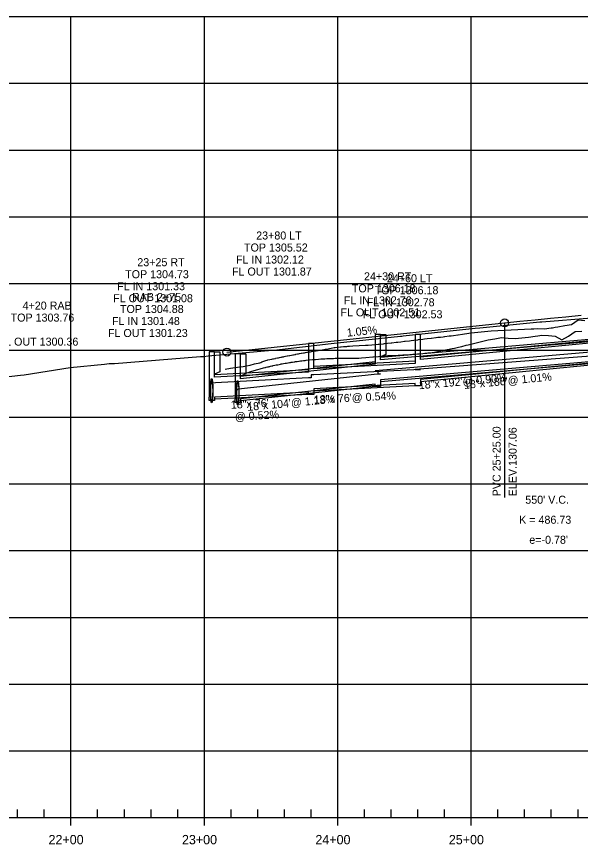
# Model space of a CAD drawing. Extents: x 670877 to 686811, y 705985 to 708501.
# Drawn here: x 685636 to 686059, y 707873 to 708493 of the extents above; entities that cross this region are included whole.
import ezdxf

# ---------------------------------------------------------------- set-up
doc = ezdxf.new("R2010")
doc.units = 0
for name, color, linetype in [('30', 7, 'Continuous'), ('37', 7, 'Continuous'), ('DRAINAGE_HGL LEFT', 7, 'Continuous'), ('DRAINAGE_HGL RIGHT', 7, 'Continuous'), ('Profile Drainage Annot Left', 7, 'Continuous'), ('Profile Drainage Annot Right', 7, 'Continuous'), ('R_Drainage Extensions_LEFT', 7, 'Continuous'), ('R_Drainage Extensions_RIGHT', 7, 'Continuous'), ('R_Drainage LEFT', 7, 'Continuous'), ('R_Drainage RIGHT', 7, 'Continuous'), ('R_Exist Surface', 7, 'Continuous'), ('R_Profile Work Left', 7, 'Continuous'), ('R_Proposed Const Limits', 7, 'Continuous'), ('R_Vert Alg', 7, 'Continuous'), ('R_Vert Alg Annot', 7, 'Continuous')]:
    doc.layers.add(name, color=color, linetype=linetype)

msp = doc.modelspace()

# ---------------------------------------------------------------- linework, layer by layer
at = {"layer": '37'}
for p, q in [((684477.28, 708492.85), (686777.28, 708492.85)), ((685677.28, 707892.85), (685677.28, 708492.85)), ((685777.28, 707892.85), (685777.28, 708492.85)), ((685877.28, 707892.85), (685877.28, 708492.85)), ((685977.28, 707892.85), (685977.28, 708492.85)), ((684477.28, 708442.85), (686777.28, 708442.85)), ((684477.28, 708392.85), (686777.28, 708392.85)), ((684477.28, 708342.85), (686777.28, 708342.85)), ((684477.28, 708292.85), (686777.28, 708292.85)), ((684477.28, 708242.85), (686777.28, 708242.85)), ((684477.28, 708192.85), (686777.28, 708192.85)), ((684477.28, 708142.85), (686777.28, 708142.85)), ((684477.28, 708092.85), (686777.28, 708092.85)), ((684477.28, 708042.85), (686777.28, 708042.85)), ((684477.28, 707992.85), (686777.28, 707992.85)), ((684477.28, 707942.85), (686777.28, 707942.85)), ((685637.28, 707892.85), (685637.28, 707898.85)), ((685657.28, 707892.85), (685657.28, 707898.85)), ((685697.28, 707892.85), (685697.28, 707898.85)), ((685717.28, 707892.85), (685717.28, 707898.85)), ((685737.28, 707892.85), (685737.28, 707898.85)), ((685757.28, 707892.85), (685757.28, 707898.85)), ((685797.28, 707892.85), (685797.28, 707898.85)), ((685817.28, 707892.85), (685817.28, 707898.85)), ((685837.28, 707892.85), (685837.28, 707898.85)), ((685857.28, 707892.85), (685857.28, 707898.85)), ((685897.28, 707892.85), (685897.28, 707898.85)), ((685917.28, 707892.85), (685917.28, 707898.85)), ((685937.28, 707892.85), (685937.28, 707898.85)), ((685957.28, 707892.85), (685957.28, 707898.85)), ((685997.28, 707892.85), (685997.28, 707898.85)), ((686017.28, 707892.85), (686017.28, 707898.85)), ((686037.28, 707892.85), (686037.28, 707898.85)), ((686057.28, 707892.85), (686057.28, 707898.85)), ((684477.28, 707892.85), (686777.28, 707892.85)), ((685677.28, 707886.85), (685677.28, 707892.85)), ((685777.28, 707886.85), (685777.28, 707892.85)), ((685877.28, 707886.85), (685877.28, 707892.85)), ((685977.28, 707886.85), (685977.28, 707892.85))]:
    msp.add_line(p, q, dxfattribs=at)
at = {"layer": 'DRAINAGE_HGL LEFT'}
msp.add_lwpolyline([(686452.28, 708277.68), (686454.28, 708277.68), (686454.28, 708277.68), (686454.28, 708277.68), (686340.29, 708272.6), (686342.29, 708272.6), (686342.29, 708264.29), (686344.29, 708264.29), (686125.29, 708244.79), (686127.29, 708244.79), (686127.29, 708243.32), (686129.3, 708243.32), (685935.28, 708228.55), (685937.28, 708228.55), (685937.28, 708228.55), (685939.3, 708228.55), (685859.24, 708224.45), (685857.24, 708224.45), (685857.24, 708222.25), (685855.24, 708222.25), (685780.74, 708218.25), (685782.77, 708218.25)], dxfattribs=at)
at = {"layer": 'DRAINAGE_HGL RIGHT'}
msp.add_lwpolyline([(686477.28, 708278.42), (686450.04, 708277.56), (686452.28, 708277.56), (686452.28, 708275.36), (686454.28, 708275.36), (686340.29, 708272.17), (686342.29, 708272.17), (686342.29, 708265.24), (686344.29, 708265.24), (686100.28, 708246.64), (686102.28, 708246.64), (686102.28, 708244.78), (686104.28, 708244.78), (685905.28, 708227.58), (685907.28, 708227.58), (685907.28, 708225.28), (685909.33, 708225.28), (685800.25, 708213.48), (685802.28, 708213.48)], dxfattribs=at)
at = {"layer": 'R_Drainage Extensions_LEFT'}
msp.add_lwpolyline([(685784.8, 708241.65), (685788.8, 708241.65), (685788.8, 708226.65), (685784.8, 708224.98), (685784.8, 708241.65)], dxfattribs=at)
at = {"layer": 'R_Drainage Extensions_RIGHT'}
for points in [[(685909.3, 708254.65), (685913.3, 708254.65), (685913.3, 708239.65), (685909.3, 708237.98), (685909.3, 708254.65)], [(685804.31, 708240.15), (685808.31, 708240.15), (685808.31, 708225.15), (685804.31, 708223.48), (685804.31, 708240.15)]]:
    msp.add_lwpolyline(points, dxfattribs=at)
at = {"layer": 'R_Drainage LEFT'}
for points in [[(685939.29, 708254.65), (685935.28, 708254.65)], [(685935.28, 708254.65), (685935.28, 708232.94)], [(686125.28, 708255.73), (685939.29, 708237.7)], [(685939.29, 708236.04), (685939.29, 708254.65)], [(686125.28, 708254.06), (685939.29, 708236.04)], [(685859.24, 708248), (685855.24, 708248)], [(685855.24, 708248), (685855.24, 708226.55)], [(685859.24, 708229.05), (685859.24, 708248)], [(685784.8, 708241.65), (685780.74, 708241.65)], [(685780.74, 708241.65), (685780.74, 708207.65)], [(685784.8, 708222.86), (685784.8, 708241.65)], [(685935.28, 708234.61), (685859.24, 708230.71)], [(686125.28, 708239.06), (685939.29, 708221.04)], [(686125.28, 708237.39), (685939.29, 708219.37)], [(685855.24, 708228.21), (685784.8, 708224.53)], [(685935.28, 708232.94), (685859.24, 708229.05)], [(685855.24, 708226.55), (685784.8, 708222.86)], [(685935.28, 708217.94), (685859.24, 708214.05)], [(685935.28, 708216.28), (685859.24, 708212.38)], [(685935.28, 708216.28), (685935.28, 708217.94)], [(685939.29, 708216.28), (685935.28, 708216.28)], [(685939.29, 708221.04), (685939.29, 708216.28)], [(685855.24, 708211.55), (685784.8, 708207.86)], [(685855.24, 708209.88), (685784.8, 708206.19)], [(685855.24, 708209.88), (685855.24, 708211.55)], [(685859.24, 708209.88), (685855.24, 708209.88)], [(685859.24, 708214.05), (685859.24, 708209.88)], [(685780.74, 708205.15), (685780.74, 708207.65)], [(685784.8, 708205.15), (685780.74, 708205.15)], [(685784.8, 708207.86), (685784.8, 708205.15)]]:
    msp.add_lwpolyline(points, dxfattribs=at)
for major_axis in [(0, 9.17), (0, 7.5)]:
    msp.add_ellipse((685782.77, 708212.65), major_axis=major_axis, ratio=0.1, dxfattribs=at)
at = {"layer": 'R_Drainage RIGHT'}
for points in [[(685909.3, 708254.65), (685905.25, 708254.65)], [(685905.25, 708254.65), (685905.25, 708232.51)], [(685909.3, 708235.8), (685909.3, 708254.65)], [(686100.28, 708253.97), (685909.3, 708237.46)], [(686100.28, 708252.3), (685909.3, 708235.8)], [(685804.31, 708240.15), (685800.25, 708240.15)], [(685800.25, 708240.15), (685800.25, 708206.15)], [(685804.31, 708221.59), (685804.31, 708240.15)], [(685905.25, 708234.17), (685804.31, 708223.25)], [(686100.28, 708237.3), (685909.3, 708220.8)], [(686100.28, 708235.64), (685909.3, 708219.13)], [(685905.25, 708232.51), (685804.31, 708221.59)], [(685905.25, 708217.51), (685804.31, 708206.59)], [(685905.25, 708215.84), (685804.31, 708204.92)], [(685905.25, 708215.84), (685905.25, 708217.51)], [(685909.3, 708215.84), (685905.25, 708215.84)], [(685909.3, 708220.8), (685909.3, 708215.84)], [(685800.25, 708203.65), (685800.25, 708206.15)], [(685804.31, 708203.65), (685800.25, 708203.65)], [(685804.31, 708206.59), (685804.31, 708203.65)]]:
    msp.add_lwpolyline(points, dxfattribs=at)
for major_axis in [(0, 9.17), (0, 7.5)]:
    msp.add_ellipse((685802.28, 708211.15), major_axis=major_axis, ratio=0.1, dxfattribs=at)
at = {"layer": 'R_Exist Surface'}
msp.add_lwpolyline([(685604.44, 708220.24), (685639.36, 708224.31), (685642.32, 708224.57), (685676.57, 708229.96), (685676.66, 708230.02), (685702.33, 708232.38), (685705.82, 708232.94), (685709.78, 708233.07), (685709.92, 708233.09), (685774.41, 708238.12), (685776.86, 708238.34), (685780.04, 708238.66), (685827.99, 708242.87), (685829.27, 708243.02), (685872.33, 708247.91), (685924.27, 708253.49), (685925.25, 708253.58), (685926.21, 708253.71), (685980.13, 708259.39), (685980.3, 708259.4), (685983.59, 708259.74), (686028.68, 708264.16), (686028.9, 708264.26), (686030.1, 708264.31), (686067.48, 708267.1)], dxfattribs=at)
at = {"layer": 'R_Profile Work Left'}
msp.add_lwpolyline([(685810.18, 708226.31), (685812.2, 708226.96), (685814.68, 708227.73), (685817.32, 708228.51), (685819, 708228.97), (685821.48, 708229.64), (685822.54, 708229.91), (685822.99, 708230.02), (685823.59, 708230.17), (685824.65, 708230.43), (685825.34, 708230.59), (685825.72, 708230.68), (685826.33, 708230.83), (685826.79, 708230.93), (685826.94, 708230.97), (685827.86, 708231.17), (685828.35, 708231.28), (685828.54, 708231.33), (685828.93, 708231.41), (685830.01, 708231.65), (685830.13, 708231.67), (685831.1, 708231.88), (685831.59, 708231.98), (685831.72, 708232), (685832.19, 708232.1), (685833.28, 708232.32), (685833.32, 708232.33), (685834.38, 708232.53), (685834.8, 708232.61), (685834.92, 708232.64), (685835.43, 708232.73), (685835.48, 708232.74), (685836.53, 708232.94), (685836.59, 708232.95), (685837.71, 708233.15), (685838.14, 708233.23), (685838.63, 708233.31), (685838.83, 708233.35), (685839.77, 708233.51), (685839.95, 708233.54), (685841.08, 708233.73), (685841.4, 708233.78), (685841.85, 708233.85), (685842.22, 708233.91), (685843.06, 708234.05), (685843.37, 708234.09), (685844.52, 708234.27), (685844.73, 708234.3), (685845.09, 708234.35), (685845.67, 708234.44), (685846.42, 708234.54), (685846.84, 708234.6), (685848.01, 708234.76), (685848.13, 708234.78), (685848.39, 708234.81), (685849.19, 708234.91), (685849.87, 708235), (685850.37, 708235.06), (685851.57, 708235.2), (685851.64, 708235.21), (685851.76, 708235.23), (685852.77, 708235.34), (685853.62, 708235.43), (685855.89, 708235.67), (685855.94, 708235.67), (685858.25, 708235.89), (685860.29, 708236.06), (685860.56, 708236.08), (685862.86, 708236.25), (685864.65, 708236.37), (685865.16, 708236.4), (685867.45, 708236.53), (685869.1, 708236.61), (685869.97, 708236.65), (685872.61, 708236.78), (685874.09, 708236.85), (685875.26, 708236.91), (685877.91, 708237.01), (685878.09, 708237.01), (685879.08, 708237.01), (685883.07, 708236.99), (685888.05, 708236.97), (685893.04, 708237.03), (685895.04, 708237.18), (685898.15, 708237.42), (685903.44, 708237.87), (685904.02, 708237.92), (685907.71, 708238.26), (685909.01, 708238.38), (685911.4, 708238.62), (685914.6, 708238.84), (685915.09, 708238.86), (685918.78, 708239.01), (685920.19, 708239.07), (685922.48, 708239.18), (685925.77, 708239.34), (685926.18, 708239.36), (685929.87, 708239.57), (685931.35, 708239.69), (685933.57, 708239.89), (685936.92, 708240.18), (685937.27, 708240.22), (685940.97, 708240.56), (685942.48, 708240.7), (685944.67, 708240.91), (685948.04, 708241.25), (685948.36, 708241.29), (685952.01, 708241.85), (685952.04, 708241.85), (685953.59, 708242.18), (685955.72, 708242.63), (685958.04, 708243.13), (685959.12, 708243.36), (685959.39, 708243.42), (685963.04, 708244.22), (685964.63, 708244.58), (685966.64, 708245.03), (685969.91, 708245.77), (685970.1, 708245.81), (685973.57, 708246.65), (685975.07, 708247.02), (685980.05, 708248.28), (685985.03, 708249.53), (685990.02, 708250.66), (685995.01, 708251.55), (686000, 708252.43), (686005.03, 708251.96), (686010.06, 708251.62), (686015.07, 708252.12), (686020.07, 708252.62), (686025.07, 708253.43), (686027.06, 708253.76), (686030.06, 708254.24), (686035.09, 708253.95), (686040.12, 708253.41), (686045.23, 708250.78), (686050.16, 708253.53), (686055.07, 708256.97), (686060.08, 708257.29)], dxfattribs=at)
at = {"layer": 'R_Proposed Const Limits'}
msp.add_lwpolyline([(685792.84, 708228.79), (685796.95, 708229.43), (685800.31, 708229.94), (685800.53, 708229.98), (685803.47, 708230.42), (685806.3, 708230.85), (685808.93, 708231.24), (685811.47, 708231.62), (685814.82, 708232.82), (685818.9, 708233.52), (685819.57, 708233.77), (685820.36, 708234.11), (685821.84, 708234.75), (685823.35, 708235.27), (685824.29, 708235.48), (685824.3, 708235.49), (685824.85, 708235.61), (685826.27, 708235.92), (685826.41, 708235.95), (685827.7, 708236.23), (685828.52, 708236.41), (685828.61, 708236.43), (685829.14, 708236.54), (685830.58, 708236.85), (685830.64, 708236.86), (685832.04, 708237.16), (685832.77, 708237.31), (685832.89, 708237.34), (685833.51, 708237.46), (685834.6, 708237.69), (685834.9, 708237.75), (685834.98, 708237.77), (685835.46, 708237.86), (685836.31, 708238.04), (685836.46, 708238.07), (685837.05, 708238.19), (685837.16, 708238.21), (685837.95, 708238.37), (685839.2, 708238.62), (685839.45, 708238.67), (685840.95, 708238.96), (685841.36, 708239.04), (685841.42, 708239.05), (685842.45, 708239.25), (685843.52, 708239.46), (685843.96, 708239.54), (685843.96, 708239.54), (685845.47, 708239.83), (685845.66, 708239.86), (685845.7, 708239.87), (685846.98, 708240.11), (685847.88, 708240.28), (685848.5, 708240.39), (685849.89, 708240.64), (685850.01, 708240.66), (685850.07, 708240.67), (685851.53, 708240.93), (685852.27, 708241.06), (685853.05, 708241.2), (685854.13, 708241.39), (685854.47, 708241.45), (685854.57, 708241.47), (685856.08, 708241.73), (685856.68, 708241.83), (685857.59, 708241.98), (685858.37, 708242.11), (685858.9, 708242.2), (685859.1, 708242.24), (685860.61, 708242.49), (685861.13, 708242.57), (685862.61, 708242.81), (685863.36, 708242.93), (685865.61, 708243.29), (685866.85, 708243.49), (685867.86, 708243.64), (685870.11, 708243.99), (685871.11, 708244.18), (685872.37, 708244.45), (685874.64, 708244.85), (685875.37, 708244.98), (685876.92, 708245.23), (685879.21, 708245.57), (685879.66, 708245.59), (685881.51, 708245.68), (685883.82, 708245.8), (685883.99, 708245.81), (685884.86, 708245.86), (685886.14, 708245.93), (685888.55, 708246.09), (685893.32, 708246.4), (685898.09, 708246.65), (685900, 708246.77), (685902.85, 708246.98), (685907.61, 708247.39), (685908.28, 708247.45), (685911.39, 708247.77), (685912.37, 708247.88), (685914.53, 708248.12), (685917.28, 708248.44), (685917.82, 708248.51), (685921.11, 708248.89), (685922.28, 708249.02), (685924.41, 708249.27), (685927.28, 708249.61), (685927.71, 708249.66), (685931.01, 708250.06), (685932.28, 708250.21), (685934.32, 708250.45), (685937.28, 708250.8), (685937.62, 708250.85), (685940.93, 708251.24), (685942.28, 708251.4), (685944.24, 708251.64), (685947.28, 708252), (685947.55, 708252.03), (685950.85, 708252.43), (685950.86, 708252.43), (685952.28, 708252.6), (685954.16, 708252.82), (685956.31, 708253.08), (685957.28, 708253.19), (685957.47, 708253.22), (685960.77, 708253.61), (685962.28, 708253.79), (685964.07, 708254), (685967.28, 708254.42), (685967.37, 708254.43), (685970.66, 708254.94), (685972.28, 708255.19), (685977.28, 708255.97), (685982.28, 708256.53), (685987.28, 708257.04), (685992.28, 708257.42), (685997.28, 708257.66), (686002.28, 708257.91), (686007.28, 708258.15), (686012.28, 708258.4), (686017.28, 708258.64), (686022.28, 708258.88), (686024.28, 708258.98), (686027.28, 708259.12), (686032.28, 708258.95), (686037.28, 708259.6), (686038.28, 708259.77), (686040.28, 708260.12), (686042.28, 708260.47), (686047.28, 708261.33), (686052.28, 708262.2), (686057.28, 708265.81), (686062.28, 708265.27)], dxfattribs=at)
at = {"layer": 'R_Vert Alg'}
msp.add_line((685794.19, 708241.55), (686002.28, 708263.43), dxfattribs=at)
msp.add_lwpolyline([(686002.28, 708263.43), (686013.74, 708264.62), (686025.19, 708265.79), (686036.65, 708266.92), (686048.11, 708268.03), (686059.57, 708269.12)], dxfattribs=at)
for centre in [(686002.28, 708263.43), (685794.19, 708241.55)]:
    msp.add_circle(centre, 3, dxfattribs=at)
at = {"layer": 'R_Vert Alg Annot'}
msp.add_line((686002.28, 708263.43), (686002.28, 708132.53), dxfattribs=at)

# ---------------------------------------------------------------- texts
at = {"layer": '30'}
for s, p in [('22+00', (685660.47, 707872.85)), ('23+00', (685760.47, 707872.85)), ('24+00', (685860.47, 707872.85)), ('25+00', (685960.47, 707872.85))]:
    msp.add_text(s, height=7, dxfattribs=at).set_placement(p)
at = {"layer": 'Profile Drainage Annot Left'}
for s, p in [('23+80 LT ', (685816.09, 708325.86)), ('TOP 1305.52', (685806.98, 708316.86)), ('FL IN 1302.12', (685800.98, 708307.86)), ('FL OUT 1301.87', (685797.97, 708298.86)), ('24+60 LT', (685914.05, 708293.86)), ('TOP 1306.18', (685904.95, 708284.86)), ('RAB 2+75', (685723.01, 708279.82)), ('4+20 RAB', (685641.02, 708273.36)), ('FL IN 1302.78', (685898.95, 708275.86)), ('TOP 1304.88', (685714.02, 708270.82)), ('FL OUT 1302.53', (685895.93, 708266.86)), ('TOP 1303.76', (685632.05, 708264.36)), ('FL IN 1301.48', (685708.02, 708261.82)), ('FL OUT 1301.23', (685705.01, 708252.82)), ('FL OUT 1300.36', (685623.05, 708246.36))]:
    msp.add_text(s, height=6, dxfattribs=at).set_placement(p)
for s, rotation, p in [('18"x 188\'@ 1.01%', 5.53462, (685972.09, 708213.92)), ('18"x 76\'@ 0.54%', 2.93186, (685859.45, 708202.92)), ('18"x 76\'', 2.99653, (685797.23, 708199.05)), ('@ 0.52%', 2.99653, (685800.25, 708190.19))]:
    msp.add_text(s, height=6, rotation=rotation, dxfattribs=at).set_placement(p)
at = {"layer": 'Profile Drainage Annot Right'}
for s, p in [('23+25 RT', (685727, 708305.86)), ('TOP 1304.73', (685717.89, 708296.86)), ('24+30 RT', (685896.89, 708295.29)), ('FL IN 1301.33', (685711.89, 708287.86)), ('TOP 1306.18', (685887.79, 708286.29)), ('FL OUT 1301.08', (685708.9, 708278.86)), ('FL IN 1302.76', (685881.78, 708277.29)), ('FL OUT 1302.51', (685879.22, 708268.29))]:
    msp.add_text(s, height=6, dxfattribs=at).set_placement(p)
for s, rotation, p in [('18"x 192\'@ 0.90%', 4.93996, (685938.16, 708213.68)), ('18"x 104\'@ 1.13%', 5.34216, (685809.61, 708197.43))]:
    msp.add_text(s, height=6, rotation=rotation, dxfattribs=at).set_placement(p)
at = {"layer": 'R_Vert Alg Annot'}
for s, rotation, p in [('1.05%', 6.00299, (685884.3, 708253.03)), ('PVC 25+25.00', 90, (685999.28, 708133.48)), ('ELEV.1307.06', 90, (686011.28, 708133.48))]:
    msp.add_text(s, height=6, rotation=rotation, dxfattribs=at).set_placement(p)
for s, p in [("550' V.C.", (686017.78, 708127.95)), ('K = 486.73', (686013.19, 708112.95)), ("e=-0.78'", (686020.78, 708097.95))]:
    msp.add_text(s, height=6, dxfattribs=at).set_placement(p)

doc.saveas('drawing.dxf')
